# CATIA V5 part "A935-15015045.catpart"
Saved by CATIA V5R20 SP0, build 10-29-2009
Part number: A935-15015045
Source: Unknown
Property "A": "110.000"
Property "ARTICLENO": "A935-15015045"
Property "B": "30.000"
Property "BOMINFO": "A935-15015045"
Property "CODE": "A935-15015045"
Property "L": "150.000"
Property "L1": "127.860"
Property "LINA": "A935-15015045"
Property "NB": "A935-15015045"
Property "NBSYN": "$CODE."
Property "NN": "A935"
Property "NT": "VDI 3357 H-Type Cam Drivers, steel (16MnCr5)"
Property "SUPPLIER": "CF"
Property "T": "45.000"
Property "W": "150.000"
Bounding box of the stored display mesh (mm): x 0 to 150, y 0 to 45, z -150 to 0
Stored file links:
  C:\Users\Utente\Desktop\3D files A935\A935-15015045.catpart
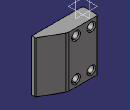
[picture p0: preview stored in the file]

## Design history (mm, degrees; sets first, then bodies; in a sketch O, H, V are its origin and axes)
Body1 "Geometry.1" (main body)
  Solid1 "A935-15015045.catpart": solid without history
